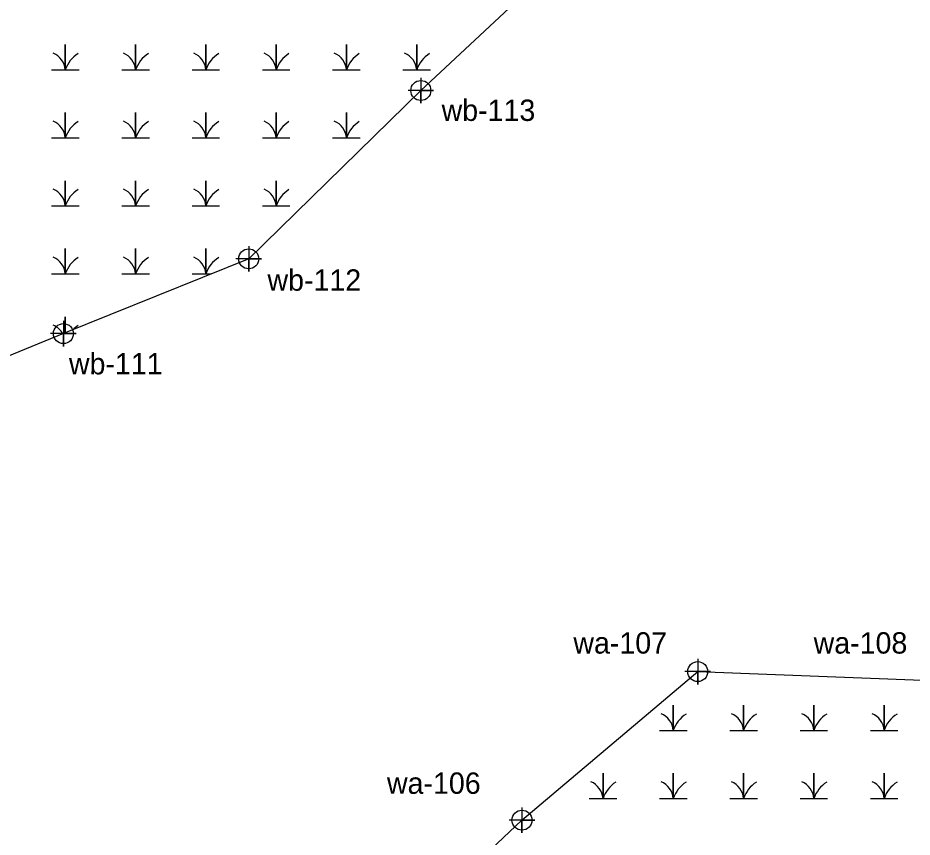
# Model space of a CAD drawing. Extents: x 2379288 to 2381905, y 330670 to 333511.
# Drawn here: x 2380484.3 to 2380693.6, y 332483.8 to 332675.5 of the extents above; entities that cross this region are included whole.
import ezdxf

# ---------------------------------------------------------------- set-up
doc = ezdxf.new("R2010")
doc.units = 0
for name, color, linetype in [('Exist Environmental Wetland Boundary', 7, 'Continuous'), ('Exist Environmental Wetland Boundary Cogo Number', 7, 'Continuous'), ('Exist Environmental Wetland Boundary Cogo Point CELL', 7, 'Continuous'), ('Exist Hydro Swamp or Marsh', 7, 'Continuous')]:
    doc.layers.add(name, color=color, linetype=linetype)

msp = doc.modelspace()

# ---------------------------------------------------------------- linework, layer by layer
at = {"layer": 'Exist Environmental Wetland Boundary'}
for points in [[(2380626.94, 332703.59), (2380578.61, 332658.53), (2380538.32, 332619.14), (2380494.95, 332601.64), (2380453.1, 332584.48), (2380406.72, 332572.38), (2380400.16, 332521.26), (2380412.11, 332496.92), (2380413.59, 332462.54), (2380386.06, 332425.71), (2380352.83, 332397.02), (2380315.67, 332385.64), (2380290.84, 332358.39), (2380295.85, 332340.3), (2380332.51, 332311.36), (2380326.97, 332300.58), (2380311.82, 332307.72), (2380244.82, 332322.56), (2380185.2, 332357.15), (2380173.71, 332371.44)], [(2380442.38, 332045.91), (2380445.79, 332068.31), (2380430.27, 332144.34), (2380463.17, 332209.13), (2380440.55, 332246.83), (2380410.07, 332261.34), (2380400.64, 332277.99), (2380430.32, 332327.14), (2380475.22, 332338.88), (2380523.99, 332375.18), (2380571.84, 332459.01), (2380602.28, 332487.78), (2380643.42, 332522.54), (2380698.01, 332520.45), (2380758.16, 332538.88), (2380814.95, 332532.8), (2380827.75, 332553.62), (2380815.96, 332612.38), (2380841.18, 332668.4), (2380857.01, 332670.65), (2380837.85, 332627.97), (2380932.82, 332657.69)]]:
    msp.add_lwpolyline(points, dxfattribs=at)
at = {"layer": 'Exist Environmental Wetland Boundary Cogo Point CELL'}
for points in [[(2380578.61, 332661.53), (2380578.61, 332655.53), (2380578.61, 332658.53), (2380581.61, 332658.53), (2380575.61, 332658.53)], [(2380538.32, 332622.14), (2380538.32, 332616.14), (2380538.32, 332619.14), (2380541.32, 332619.14), (2380535.32, 332619.14)], [(2380494.95, 332604.64), (2380494.95, 332598.64), (2380494.95, 332601.64), (2380497.95, 332601.64), (2380491.95, 332601.64)], [(2380643.42, 332525.54), (2380643.42, 332519.54), (2380643.42, 332522.54), (2380646.42, 332522.54), (2380640.42, 332522.54)], [(2380602.28, 332490.78), (2380602.28, 332484.78), (2380602.28, 332487.78), (2380605.28, 332487.78), (2380599.28, 332487.78)]]:
    msp.add_lwpolyline(points, dxfattribs=at)
for centre in [(2380578.61, 332658.53), (2380538.32, 332619.14), (2380494.95, 332601.64), (2380643.42, 332522.54), (2380602.28, 332487.78)]:
    msp.add_circle(centre, 2.34, dxfattribs=at)
at = {"layer": 'Exist Hydro Swamp or Marsh'}
for points in [[(2380492.16, 332663.35), (2380495.38, 332663.35), (2380495.38, 332669.27), (2380495.38, 332663.35), (2380498.61, 332663.35)], [(2380508.61, 332663.35), (2380511.84, 332663.35), (2380511.84, 332669.27), (2380511.84, 332663.35), (2380515.06, 332663.35)], [(2380525.06, 332663.35), (2380528.29, 332663.35), (2380528.29, 332669.27), (2380528.29, 332663.35), (2380531.51, 332663.35)], [(2380541.51, 332663.35), (2380544.74, 332663.35), (2380544.74, 332669.27), (2380544.74, 332663.35), (2380547.96, 332663.35)], [(2380557.96, 332663.35), (2380561.19, 332663.35), (2380561.19, 332669.27), (2380561.19, 332663.35), (2380564.42, 332663.35)], [(2380574.42, 332663.35), (2380577.64, 332663.35), (2380577.64, 332669.27), (2380577.64, 332663.35), (2380580.87, 332663.35)], [(2380492.16, 332647.43), (2380495.38, 332647.43), (2380495.38, 332653.35), (2380495.38, 332647.43), (2380498.61, 332647.43)], [(2380508.61, 332647.43), (2380511.84, 332647.43), (2380511.84, 332653.35), (2380511.84, 332647.43), (2380515.06, 332647.43)], [(2380525.06, 332647.43), (2380528.29, 332647.43), (2380528.29, 332653.35), (2380528.29, 332647.43), (2380531.51, 332647.43)], [(2380541.51, 332647.43), (2380544.74, 332647.43), (2380544.74, 332653.35), (2380544.74, 332647.43), (2380547.96, 332647.43)], [(2380557.96, 332647.43), (2380561.19, 332647.43), (2380561.19, 332653.35), (2380561.19, 332647.43), (2380564.42, 332647.43)], [(2380492.16, 332631.52), (2380495.38, 332631.52), (2380495.38, 332637.43), (2380495.38, 332631.52), (2380498.61, 332631.52)], [(2380508.61, 332631.52), (2380511.84, 332631.52), (2380511.84, 332637.43), (2380511.84, 332631.52), (2380515.06, 332631.52)], [(2380525.06, 332631.52), (2380528.29, 332631.52), (2380528.29, 332637.43), (2380528.29, 332631.52), (2380531.51, 332631.52)], [(2380541.51, 332631.52), (2380544.74, 332631.52), (2380544.74, 332637.43), (2380544.74, 332631.52), (2380547.96, 332631.52)], [(2380492.16, 332615.6), (2380495.38, 332615.6), (2380495.38, 332621.52), (2380495.38, 332615.6), (2380498.61, 332615.6)], [(2380508.61, 332615.6), (2380511.84, 332615.6), (2380511.84, 332621.52), (2380511.84, 332615.6), (2380515.06, 332615.6)], [(2380525.06, 332615.6), (2380528.29, 332615.6), (2380528.29, 332621.52), (2380528.29, 332615.6), (2380529.56, 332615.6)], [(2380495.38, 332601.82), (2380495.38, 332605.6), (2380495.38, 332601.82)], [(2380634.48, 332508.76), (2380637.7, 332508.76), (2380637.7, 332514.68), (2380637.7, 332508.76), (2380640.93, 332508.76)], [(2380650.93, 332508.76), (2380654.15, 332508.76), (2380654.15, 332514.68), (2380654.15, 332508.76), (2380657.38, 332508.76)], [(2380667.38, 332508.76), (2380670.6, 332508.76), (2380670.6, 332514.68), (2380670.6, 332508.76), (2380673.83, 332508.76)], [(2380683.83, 332508.76), (2380687.06, 332508.76), (2380687.06, 332514.68), (2380687.06, 332508.76), (2380690.28, 332508.76)], [(2380618.02, 332492.84), (2380621.25, 332492.84), (2380621.25, 332498.76), (2380621.25, 332492.84), (2380624.48, 332492.84)], [(2380634.48, 332492.84), (2380637.7, 332492.84), (2380637.7, 332498.76), (2380637.7, 332492.84), (2380640.93, 332492.84)], [(2380650.93, 332492.84), (2380654.15, 332492.84), (2380654.15, 332498.76), (2380654.15, 332492.84), (2380657.38, 332492.84)], [(2380667.38, 332492.84), (2380670.6, 332492.84), (2380670.6, 332498.76), (2380670.6, 332492.84), (2380673.83, 332492.84)], [(2380683.83, 332492.84), (2380687.06, 332492.84), (2380687.06, 332498.76), (2380687.06, 332492.84), (2380690.28, 332492.84)]]:
    msp.add_lwpolyline(points, dxfattribs=at)
for centre, radius, start, end in [((2380490.79, 332663.02), 4.61, 4.1403, 67.535), ((2380502.23, 332661.08), 7.21, 122.1274, 161.6222), ((2380507.24, 332663.02), 4.61, 4.1403, 67.535), ((2380518.68, 332661.08), 7.21, 122.1274, 161.6222), ((2380523.69, 332663.02), 4.61, 4.1403, 67.535), ((2380535.13, 332661.08), 7.21, 122.1274, 161.6222), ((2380540.14, 332663.02), 4.61, 4.1403, 67.535), ((2380551.58, 332661.08), 7.21, 122.1274, 161.6222), ((2380556.59, 332663.02), 4.61, 4.1403, 67.535), ((2380568.03, 332661.08), 7.21, 122.1274, 161.6222), ((2380573.04, 332663.02), 4.61, 4.1403, 67.535), ((2380584.48, 332661.08), 7.21, 122.1274, 161.6222), ((2380490.79, 332647.1), 4.61, 4.1403, 67.535), ((2380502.23, 332645.16), 7.21, 122.1274, 161.6222), ((2380507.24, 332647.1), 4.61, 4.1403, 67.535), ((2380518.68, 332645.16), 7.21, 122.1274, 161.6222), ((2380523.69, 332647.1), 4.61, 4.1403, 67.535), ((2380535.13, 332645.16), 7.21, 122.1274, 161.6222), ((2380540.14, 332647.1), 4.61, 4.1403, 67.535), ((2380551.58, 332645.16), 7.21, 122.1274, 161.6222), ((2380556.59, 332647.1), 4.61, 4.1403, 67.535), ((2380568.03, 332645.16), 7.21, 122.1274, 161.6222), ((2380490.79, 332631.18), 4.61, 4.1403, 67.535), ((2380502.23, 332629.24), 7.21, 122.1274, 161.6222), ((2380507.24, 332631.18), 4.61, 4.1403, 67.535), ((2380518.68, 332629.24), 7.21, 122.1274, 161.6222), ((2380523.69, 332631.18), 4.61, 4.1403, 67.535), ((2380535.13, 332629.24), 7.21, 122.1274, 161.6222), ((2380540.14, 332631.18), 4.61, 4.1403, 67.535), ((2380551.58, 332629.24), 7.21, 122.1274, 161.6222), ((2380490.79, 332615.27), 4.61, 4.1403, 67.535), ((2380502.23, 332613.33), 7.21, 122.1274, 161.6222), ((2380507.24, 332615.27), 4.61, 4.1403, 67.535), ((2380518.68, 332613.33), 7.21, 122.1274, 161.6222), ((2380523.69, 332615.27), 4.61, 4.1403, 67.535), ((2380535.13, 332613.33), 7.21, 122.1274, 161.6222), ((2380490.79, 332599.35), 4.61, 29.0354, 67.535), ((2380502.23, 332597.41), 7.21, 122.1274, 134.7341), ((2380633.1, 332508.43), 4.61, 4.1403, 67.535), ((2380644.54, 332506.49), 7.21, 122.1274, 161.6222), ((2380649.55, 332508.43), 4.61, 4.1403, 67.535), ((2380660.99, 332506.49), 7.21, 122.1274, 161.6222), ((2380666, 332508.43), 4.61, 4.1403, 67.535), ((2380677.45, 332506.49), 7.21, 122.1274, 161.6222), ((2380682.46, 332508.43), 4.61, 4.1403, 67.535), ((2380693.9, 332506.49), 7.21, 122.1274, 161.6222), ((2380616.65, 332492.51), 4.61, 4.1403, 67.535), ((2380628.09, 332490.57), 7.21, 122.1274, 161.6222), ((2380633.1, 332492.51), 4.61, 4.1403, 67.535), ((2380644.54, 332490.57), 7.21, 122.1274, 161.6222), ((2380649.55, 332492.51), 4.61, 4.1403, 67.535), ((2380660.99, 332490.57), 7.21, 122.1274, 161.6222), ((2380666, 332492.51), 4.61, 4.1403, 67.535), ((2380677.45, 332490.57), 7.21, 122.1274, 161.6222), ((2380682.46, 332492.51), 4.61, 4.1403, 67.535), ((2380693.9, 332490.57), 7.21, 122.1274, 161.6222)]:
    msp.add_arc(centre, radius, start, end, dxfattribs=at)

# ---------------------------------------------------------------- texts
at = {"layer": 'Exist Environmental Wetland Boundary Cogo Number'}
for s, p in [('wb-113', (2380583.47, 332651.41)), ('wb-112', (2380542.71, 332611.67)), ('wb-111', (2380496.24, 332592.1)), ('wa-107', (2380614.31, 332526.76)), ('wa-108', (2380670.55, 332526.76)), ('wa-106', (2380570.68, 332493.94))]:
    msp.add_text(s, height=5, dxfattribs=at).set_placement(p)

doc.saveas('drawing.dxf')
